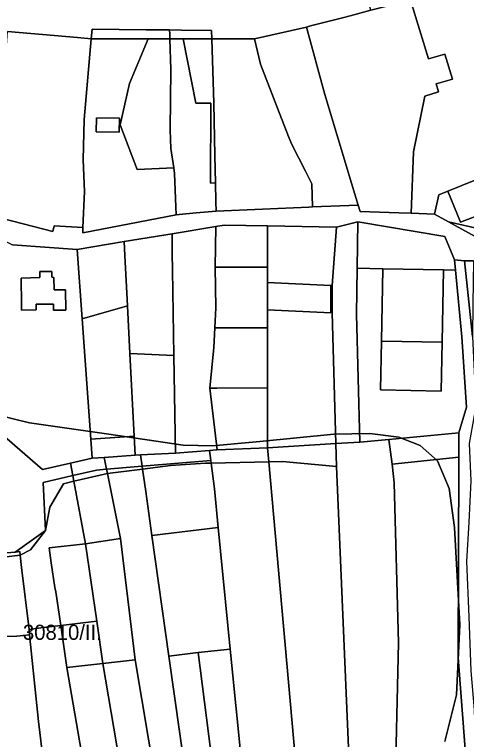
# Model space of a CAD drawing. Extents: x -535894 to -532834, y -1165802 to -1163645.
# Drawn here: x -534487.4 to -534338.4, y -1165184 to -1164945 of the extents above; entities that cross this region are included whole.
import ezdxf

# ---------------------------------------------------------------- set-up
doc = ezdxf.new("R2010")
doc.units = 0
for name, color, linetype in [('95560013', 7, 'Continuous'), ('95590013', 7, 'Continuous'), ('95600013', 7, 'Continuous'), ('95640013', 7, 'Continuous'), ('95660013', 7, 'Continuous')]:
    doc.layers.add(name, color=color, linetype=linetype)

msp = doc.modelspace()

# ---------------------------------------------------------------- linework, layer by layer
at = {"layer": '95560013'}
for points in [[(-534363.95, -1165085.07), (-534340.91, -1165082.87), (-534340.93, -1165090.96), (-534362.94, -1165093.25)], [(-534373.53, -1165086), (-534363.95, -1165085.07), (-534362.94, -1165093.25), (-534362.19, -1165099.37), (-534360.8, -1165152.21), (-534363.2, -1165257.26), (-534368.13, -1165254.92), (-534376.79, -1165251.88), (-534375.61, -1165225.35), (-534381.19, -1165093.99), (-534381.51, -1165086.49)], [(-534403.97, -1165087.87), (-534403.56, -1165092.47), (-534422.55, -1165092.92), (-534422.66, -1165092.09), (-534423.1, -1165088.71), (-534420.94, -1165088.56), (-534420.53, -1165088.55)], [(-534403.97, -1165087.87), (-534381.51, -1165086.49), (-534381.19, -1165093.99), (-534399.08, -1165092.35), (-534403.56, -1165092.47)], [(-534422.55, -1165092.92), (-534403.56, -1165092.47), (-534391.54, -1165226.66), (-534389.65, -1165251.4), (-534397.29, -1165252.4), (-534405.45, -1165253.73), (-534408.79, -1165228.57), (-534416.26, -1165154.3), (-534420.23, -1165114.18), (-534421.45, -1165101.43)], [(-534403.56, -1165092.47), (-534399.08, -1165092.35), (-534381.19, -1165093.99), (-534375.61, -1165225.35), (-534391.54, -1165226.66)], [(-534362.94, -1165093.25), (-534340.93, -1165090.96), (-534341.17, -1165157.05), (-534338.8, -1165187.24), (-534348.24, -1165186.88), (-534348.28, -1165269.23), (-534358.8, -1165260.74), (-534363.2, -1165257.26), (-534360.8, -1165152.21), (-534362.19, -1165099.37)], [(-534445.18, -1165094.85), (-534456.75, -1165096.28), (-534457.02, -1165094.93), (-534445.3, -1165093.96)], [(-534456.75, -1165096.28), (-534445.18, -1165094.85), (-534444.13, -1165102.22), (-534442.07, -1165116.76), (-534436.45, -1165156.54), (-534425.58, -1165233.37), (-534425.2, -1165235.77), (-534435.5, -1165237.88), (-534440.98, -1165197.04), (-534447.57, -1165157.79), (-534452.39, -1165117.81)], [(-534458.2, -1165158.95), (-534447.57, -1165157.79), (-534440.98, -1165197.04), (-534435.5, -1165237.88), (-534444.47, -1165239.8)]]:
    msp.add_lwpolyline(points, close=True, dxfattribs=at)
at = {"layer": '95590013'}
for points in [[(-534371.08, -1164939.34), (-534357.43, -1164937.18), (-534334.97, -1164941.39), (-534333.48, -1164948.48), (-534333.57, -1164963.39), (-534333.62, -1164973.53), (-534334.15, -1164983.38), (-534333.78, -1164990.52), (-534333.36, -1164998.76), (-534335.33, -1164999.55), (-534344.59, -1165003.27), (-534347.52, -1165004.44), (-534348.99, -1165010.79), (-534356.63, -1165010.51), (-534355.84, -1164990.24), (-534352.12, -1164971.86), (-534347.59, -1164970.48), (-534348.38, -1164967.88), (-534343.02, -1164966.25), (-534345.52, -1164958.02), (-534350.88, -1164959.65), (-534356.81, -1164940.14), (-534369.96, -1164943.59)], [(-534431.79, -1164953.01), (-534422.33, -1164953), (-534421.68, -1164974.24), (-534421.31, -1164991.48), (-534421.11, -1165000.5), (-534422.82, -1165000.59), (-534422.68, -1164974.25), (-534427.58, -1164974.26)], [(-534344.59, -1165003.27), (-534340.41, -1165013.49), (-534326.34, -1165008.07), (-534323.17, -1165006.94), (-534316.46, -1165011.48), (-534307.96, -1165011.06), (-534307.68, -1165013.89), (-534311.71, -1165018.18), (-534316.13, -1165017.8), (-534323.68, -1165017.15), (-534329.82, -1165016.63), (-534344.37, -1165013.33), (-534348.99, -1165010.79), (-534347.52, -1165004.44)], [(-534381.21, -1165015.12), (-534374.22, -1165013.39), (-534374.46, -1165028.64), (-534374.69, -1165043.74), (-534373.53, -1165086), (-534381.51, -1165086.49), (-534382.68, -1165043.37), (-534382.64, -1165034.37)], [(-534344.37, -1165013.33), (-534329.82, -1165016.63), (-534323.68, -1165017.15), (-534316.13, -1165017.8), (-534311.71, -1165018.18), (-534313.73, -1165020.34), (-534327.77, -1165022.47)], [(-534488.01, -1165020.91), (-534466.76, -1165022.45), (-534465.11, -1165045.38), (-534462.24, -1165085.02), (-534461.79, -1165091.28), (-534468.89, -1165092.92), (-534478.11, -1165095.05), (-534491.48, -1165083.48), (-534497.01, -1165041.71), (-534499.24, -1165024.85), (-534500.56, -1165014.81)], [(-534420.99, -1165014.89), (-534421.26, -1165028.31), (-534421.04, -1165041.75), (-534421.36, -1165048.3), (-534421.67, -1165054.78), (-534423.03, -1165068.16), (-534420.53, -1165088.55), (-534420.94, -1165088.56), (-534423.1, -1165088.71), (-534434.26, -1165089.65), (-534434.81, -1165057.43), (-534435.28, -1165029.23), (-534435.39, -1165023.63), (-534435.41, -1165017.27)], [(-534381.21, -1165015.12), (-534382.64, -1165034.37), (-534383.14, -1165034.35), (-534403.98, -1165033.35), (-534403.99, -1165028.33), (-534403.97, -1165014.71)], [(-534339, -1165026.19), (-534336.09, -1165026.21), (-534336.35, -1165040.51), (-534336.45, -1165051.12)], [(-534479.02, -1165029.69), (-534478.99, -1165031.69), (-534485.18, -1165031.88), (-534485.01, -1165040.52), (-534485.01, -1165042.48), (-534480.24, -1165042.39), (-534480.25, -1165040.49), (-534474.56, -1165040.45), (-534474.52, -1165042.52), (-534470.45, -1165042.5), (-534470.53, -1165035.74), (-534474.28, -1165035.76), (-534474.35, -1165031.67), (-534475.04, -1165031.63), (-534475.11, -1165029.69)], [(-534365.92, -1165028.8), (-534366.38, -1165052.71), (-534366.7, -1165068.79), (-534346.71, -1165069.18), (-534346.39, -1165053.08), (-534345.92, -1165029.2), (-534342.03, -1165029.27), (-534339.89, -1165051.28), (-534338.44, -1165074.49), (-534340.91, -1165082.87), (-534363.95, -1165085.07), (-534373.53, -1165086), (-534374.69, -1165043.74), (-534374.46, -1165028.64)], [(-534383.14, -1165034.35), (-534382.64, -1165034.37), (-534382.68, -1165043.37), (-534381.51, -1165086.49), (-534403.97, -1165087.87), (-534403.97, -1165068.1), (-534403.98, -1165048.34), (-534403.98, -1165042.36), (-534383.14, -1165043.35)], [(-534450.11, -1165041.01), (-534449.3, -1165056.79), (-534447.89, -1165084.07), (-534462.24, -1165085.02), (-534465.11, -1165045.38)], [(-534403.98, -1165048.34), (-534403.97, -1165068.1), (-534420.73, -1165068.15), (-534423.03, -1165068.16), (-534421.67, -1165054.78), (-534421.36, -1165048.3)], [(-534366.38, -1165052.71), (-534346.39, -1165053.08), (-534346.71, -1165069.18), (-534366.7, -1165068.79)], [(-534434.81, -1165057.43), (-534434.26, -1165089.65), (-534445.83, -1165090.22), (-534447.57, -1165090.34), (-534447.89, -1165084.07), (-534449.3, -1165056.79)], [(-534420.73, -1165068.15), (-534403.97, -1165068.1), (-534403.97, -1165087.87), (-534420.53, -1165088.55), (-534423.03, -1165068.16)], [(-534422.55, -1165092.92), (-534424.46, -1165092.97), (-534435.96, -1165093.7), (-534445.18, -1165094.85), (-534445.3, -1165093.96), (-534422.66, -1165092.09)], [(-534460.35, -1165095.21), (-534457.02, -1165094.93), (-534456.75, -1165096.28), (-534467.78, -1165098.88), (-534468.13, -1165097.01)], [(-534424.46, -1165092.97), (-534422.55, -1165092.92), (-534421.45, -1165101.43), (-534420.23, -1165114.18), (-534442.07, -1165116.76), (-534444.13, -1165102.22), (-534445.18, -1165094.85), (-534435.96, -1165093.7)], [(-534467.78, -1165098.88), (-534456.75, -1165096.28), (-534452.39, -1165117.81), (-534463.97, -1165119.47)], [(-534472.14, -1165146.47), (-534460.23, -1165145.05), (-534458.2, -1165158.95), (-534470.12, -1165160.31)], [(-534478.68, -1165147.25), (-534472.14, -1165146.47), (-534470.12, -1165160.31), (-534455.8, -1165243.06), (-534461.02, -1165244.38), (-534470.72, -1165237.94), (-534474.69, -1165217.27), (-534479.49, -1165178.1), (-534482.37, -1165149.5), (-534482.54, -1165147.81)], [(-534426.83, -1165155.34), (-534416.26, -1165154.3), (-534408.79, -1165228.57), (-534417.1, -1165232.13)], [(-534436.45, -1165156.54), (-534426.83, -1165155.34), (-534417.1, -1165232.13), (-534408.79, -1165228.57), (-534405.45, -1165253.73), (-534415.33, -1165254.24), (-534421.35, -1165253.74), (-534423.92, -1165242.4), (-534425.2, -1165235.77), (-534425.58, -1165233.37)], [(-534470.12, -1165160.31), (-534458.2, -1165158.95), (-534444.47, -1165239.8), (-534455.8, -1165243.06)]]:
    msp.add_lwpolyline(points, close=True, dxfattribs=at)
at = {"layer": '95600013'}
msp.add_lwpolyline([(-534526.42, -1165144.06), (-534506.66, -1165142.89), (-534505.88, -1165150.21), (-534486.55, -1165149.95), (-534482.37, -1165149.5), (-534479.49, -1165178.1), (-534474.69, -1165217.27), (-534470.72, -1165237.94), (-534490.64, -1165243.85), (-534498.4, -1165244.45), (-534504.24, -1165246.32), (-534515.07, -1165249.99), (-534525.69, -1165253.61), (-534525.52, -1165245.33), (-534526.56, -1165167.24), (-534526.49, -1165154.6)], close=True, dxfattribs=at)
at = {"layer": '95640013'}
for points in [[(-534356.81, -1164940.14), (-534350.88, -1164959.65), (-534345.52, -1164958.02), (-534343.02, -1164966.25), (-534348.38, -1164967.88), (-534347.59, -1164970.48), (-534352.12, -1164971.86), (-534355.84, -1164990.24), (-534356.63, -1165010.51), (-534360.64, -1165010.37), (-534373.42, -1165009.91), (-534374.04, -1165007.87), (-534376.24, -1165000.61), (-534385.1, -1164971.33), (-534391.17, -1164949.12), (-534389.78, -1164948.76), (-534379.25, -1164946.03), (-534376.73, -1164945.38), (-534369.96, -1164943.59)], [(-534391.17, -1164949.12), (-534385.1, -1164971.33), (-534376.24, -1165000.61), (-534374.04, -1165007.87), (-534389.11, -1165008.45), (-534389.4, -1165000.85), (-534391.5, -1164996.69), (-534395.95, -1164987.86), (-534396.87, -1164985.71), (-534400.13, -1164977.32), (-534406.33, -1164961.38), (-534408.23, -1164953)], [(-534466.57, -1164952.61), (-534462.09, -1164953), (-534464.37, -1164979.65), (-534464.75, -1164992.87), (-534464.33, -1165003.32), (-534464.79, -1165015.17), (-534474.29, -1165014.68), (-534474.77, -1165016.57), (-534494.86, -1165011.42), (-534497.44, -1165010.75), (-534499.22, -1165009.6), (-534494.31, -1165002.21), (-534492.53, -1164986.26), (-534492.33, -1164984.55), (-534491.63, -1164978.28), (-534489.63, -1164950.63)], [(-534461.81, -1164949.81), (-534443.96, -1164950), (-534442.32, -1164950.03), (-534436.91, -1164950.08), (-534436.26, -1164950.09), (-534436.21, -1164951.47), (-534436.16, -1164953), (-534443.26, -1164953), (-534445.31, -1164953), (-534462.09, -1164953)], [(-534436.26, -1164950.09), (-534432.36, -1164950.13), (-534422.4, -1164950.24), (-534422.33, -1164953), (-534431.79, -1164953.01), (-534436.16, -1164953), (-534436.21, -1164951.47)], [(-534462.09, -1164953), (-534445.31, -1164953), (-534443.26, -1164953), (-534449.41, -1164967.75), (-534452.51, -1164981.34), (-534446.93, -1164996.06), (-534434.88, -1164995.57), (-534434.58, -1164997.44), (-534434.2, -1165008.42), (-534434.11, -1165010.99), (-534464.85, -1165016.92), (-534464.79, -1165015.17), (-534464.33, -1165003.32), (-534464.75, -1164992.87), (-534464.37, -1164979.65)], [(-534443.26, -1164953), (-534436.16, -1164953), (-534435.79, -1164963.16), (-534436.1, -1164982.98), (-534435.88, -1164989.17), (-534434.88, -1164995.57), (-534446.93, -1164996.06), (-534452.51, -1164981.34), (-534449.41, -1164967.75)], [(-534436.16, -1164953), (-534431.79, -1164953.01), (-534427.58, -1164974.26), (-534422.68, -1164974.25), (-534422.82, -1165000.59), (-534421.11, -1165000.5), (-534420.98, -1165006.79), (-534420.92, -1165009.8), (-534427.49, -1165010.4), (-534433.05, -1165010.9), (-534434.11, -1165010.99), (-534434.2, -1165008.42), (-534434.58, -1164997.44), (-534434.88, -1164995.57), (-534435.88, -1164989.17), (-534436.1, -1164982.98), (-534435.79, -1164963.16)], [(-534422.33, -1164953), (-534408.23, -1164953), (-534406.33, -1164961.38), (-534400.13, -1164977.32), (-534396.87, -1164985.71), (-534395.95, -1164987.86), (-534391.5, -1164996.69), (-534389.4, -1165000.85), (-534389.11, -1165008.45), (-534390.4, -1165008.5), (-534420.92, -1165009.8), (-534420.98, -1165006.79), (-534421.11, -1165000.5), (-534421.31, -1164991.48), (-534421.68, -1164974.24)], [(-534460.38, -1164979.04), (-534452.78, -1164979.17), (-534452.83, -1164983.78), (-534460.47, -1164983.64)], [(-534460.38, -1164979.04), (-534460.47, -1164983.64), (-534452.83, -1164983.78), (-534452.78, -1164979.17)], [(-534326.13, -1164999.26), (-534323.17, -1165006.94), (-534326.34, -1165008.07), (-534340.41, -1165013.49), (-534344.59, -1165003.27), (-534335.33, -1164999.55), (-534334.18, -1165002.41), (-534329.35, -1165000.46), (-534328.08, -1164999.98)], [(-534374.22, -1165013.39), (-534345.52, -1165018.15), (-534342.35, -1165025.88), (-534342.03, -1165029.27), (-534345.92, -1165029.2), (-534365.92, -1165028.8), (-534374.46, -1165028.64)], [(-534403.97, -1165014.71), (-534403.99, -1165028.33), (-534407.71, -1165028.33), (-534419.68, -1165028.32), (-534421.26, -1165028.31), (-534420.99, -1165014.89), (-534418.3, -1165014.45)], [(-534435.41, -1165017.27), (-534435.39, -1165023.63), (-534435.28, -1165029.23), (-534434.81, -1165057.43), (-534449.3, -1165056.79), (-534450.11, -1165041.01), (-534450.96, -1165024.44), (-534451.2, -1165019.87)], [(-534451.2, -1165019.87), (-534450.96, -1165024.44), (-534450.11, -1165041.01), (-534465.11, -1165045.38), (-534466.76, -1165022.45)], [(-534342.35, -1165025.88), (-534339, -1165026.19), (-534336.45, -1165051.12), (-534335.3, -1165074.14), (-534337.54, -1165086.43), (-534336.94, -1165098.71), (-534337.66, -1165112.41), (-534338.34, -1165125.36), (-534337.61, -1165143.65), (-534336.91, -1165161.4), (-534335.9, -1165174.28), (-534335.39, -1165187.36), (-534338.8, -1165187.24), (-534341.17, -1165157.05), (-534340.93, -1165090.96), (-534340.91, -1165082.87), (-534338.44, -1165074.49), (-534339.89, -1165051.28), (-534342.03, -1165029.27)], [(-534479.02, -1165029.69), (-534475.11, -1165029.69), (-534475.04, -1165031.63), (-534474.35, -1165031.67), (-534474.28, -1165035.76), (-534470.53, -1165035.74), (-534470.45, -1165042.5), (-534474.52, -1165042.52), (-534474.56, -1165040.45), (-534480.25, -1165040.49), (-534480.24, -1165042.39), (-534485.01, -1165042.48), (-534485.01, -1165040.52), (-534485.18, -1165031.88), (-534478.99, -1165031.69)], [(-534419.68, -1165028.32), (-534407.71, -1165028.33), (-534403.99, -1165028.33), (-534403.98, -1165033.35), (-534403.98, -1165042.36), (-534403.98, -1165048.34), (-534421.36, -1165048.3), (-534421.04, -1165041.75), (-534421.26, -1165028.31)], [(-534345.92, -1165029.2), (-534346.39, -1165053.08), (-534366.38, -1165052.71), (-534365.92, -1165028.8)], [(-534403.98, -1165033.35), (-534383.14, -1165034.35), (-534383.14, -1165043.35), (-534403.98, -1165042.36)], [(-534447.89, -1165084.07), (-534447.57, -1165090.34), (-534457.81, -1165091.02), (-534461.79, -1165091.28), (-534462.24, -1165085.02)], [(-534447.57, -1165090.34), (-534445.83, -1165090.22), (-534445.3, -1165093.96), (-534457.02, -1165094.93), (-534457.81, -1165091.02)], [(-534434.26, -1165089.65), (-534423.1, -1165088.71), (-534422.66, -1165092.09), (-534445.3, -1165093.96), (-534445.83, -1165090.22)], [(-534461.79, -1165091.28), (-534457.81, -1165091.02), (-534457.02, -1165094.93), (-534460.35, -1165095.21), (-534468.13, -1165097.01), (-534468.89, -1165092.92)], [(-534467.78, -1165098.88), (-534471.25, -1165099.69), (-534475.74, -1165107.41), (-534477.12, -1165115.1), (-534477.91, -1165099.28), (-534468.13, -1165097.01)], [(-534471.25, -1165099.69), (-534467.78, -1165098.88), (-534463.97, -1165119.47), (-534475.96, -1165120.89), (-534475.24, -1165125.77), (-534474.04, -1165133.88), (-534473.77, -1165135.32), (-534472.14, -1165146.47), (-534478.68, -1165147.25), (-534482.54, -1165147.81), (-534485.11, -1165127.29), (-534485.47, -1165123.31), (-534482.11, -1165121.5), (-534477.12, -1165115.1), (-534475.74, -1165107.41)], [(-534442.07, -1165116.76), (-534420.23, -1165114.18), (-534416.26, -1165154.3), (-534426.83, -1165155.34), (-534436.45, -1165156.54)], [(-534482.11, -1165121.5), (-534485.47, -1165123.31), (-534485.59, -1165122.03), (-534487.16, -1165122.22), (-534477.12, -1165115.1)], [(-534463.97, -1165119.47), (-534452.39, -1165117.81), (-534447.57, -1165157.79), (-534458.2, -1165158.95), (-534460.23, -1165145.05)], [(-534463.97, -1165119.47), (-534460.23, -1165145.05), (-534472.14, -1165146.47), (-534473.77, -1165135.32), (-534474.04, -1165133.88), (-534475.24, -1165125.77), (-534475.96, -1165120.89)], [(-534485.59, -1165122.03), (-534485.47, -1165123.31), (-534508.47, -1165126.04), (-534508.71, -1165123.9), (-534487.16, -1165122.22)], [(-534508.47, -1165126.04), (-534485.47, -1165123.31), (-534485.11, -1165127.29), (-534482.54, -1165147.81), (-534482.37, -1165149.5), (-534486.55, -1165149.95), (-534505.88, -1165150.21), (-534506.66, -1165142.89), (-534507.16, -1165138.28), (-534508.07, -1165129.82)]]:
    msp.add_lwpolyline(points, close=True, dxfattribs=at)
for points in [[(-534369.96, -1164943.59), (-534376.73, -1164945.38), (-534379.25, -1164946.03), (-534389.78, -1164948.76), (-534391.17, -1164949.12), (-534408.23, -1164953), (-534422.33, -1164953), (-534422.4, -1164950.24), (-534432.36, -1164950.13), (-534436.26, -1164950.09), (-534436.91, -1164950.08), (-534442.32, -1164950.03), (-534443.96, -1164950), (-534461.81, -1164949.81), (-534462.09, -1164953), (-534466.57, -1164952.61), (-534489.63, -1164950.63)], [(-534494.86, -1165011.42), (-534474.77, -1165016.57), (-534474.29, -1165014.68), (-534464.79, -1165015.17), (-534464.85, -1165016.92), (-534434.11, -1165010.99), (-534433.05, -1165010.9), (-534427.49, -1165010.4), (-534420.92, -1165009.8), (-534390.4, -1165008.5), (-534389.11, -1165008.45), (-534374.04, -1165007.87), (-534373.42, -1165009.91), (-534360.64, -1165010.37), (-534356.63, -1165010.51), (-534348.99, -1165010.79), (-534344.37, -1165013.33), (-534327.77, -1165022.47)], [(-534336.09, -1165026.21), (-534339, -1165026.19), (-534342.35, -1165025.88), (-534345.52, -1165018.15), (-534374.22, -1165013.39), (-534381.21, -1165015.12), (-534403.97, -1165014.71), (-534418.3, -1165014.45), (-534420.99, -1165014.89), (-534435.41, -1165017.27), (-534451.2, -1165019.87), (-534466.76, -1165022.45), (-534488.01, -1165020.91)], [(-534491.48, -1165083.48), (-534478.11, -1165095.05), (-534468.89, -1165092.92), (-534468.13, -1165097.01), (-534477.91, -1165099.28), (-534477.12, -1165115.1), (-534487.16, -1165122.22), (-534508.71, -1165123.9)]]:
    msp.add_lwpolyline(points, dxfattribs=at)
at = {"layer": '95660013'}
for points in [[(-534345.52, -1165184.73), (-534341.69, -1165169.28), (-534340.58, -1165146.18), (-534342.33, -1165114.17), (-534344.08, -1165101.26), (-534347.997, -1165092.167), (-534353.64, -1165087.09), (-534360.73, -1165084.38), (-534370.2, -1165083.11), (-534382.16, -1165083.358), (-534406.52, -1165085.73), (-534422.13, -1165087.25), (-534431.76, -1165086.94), (-534457.09, -1165083.27), (-534482.42, -1165079.6), (-534517.62, -1165071)], [(-534517.62, -1165071), (-534482.42, -1165079.6), (-534457.09, -1165083.27), (-534431.76, -1165086.94), (-534422.13, -1165087.25), (-534406.52, -1165085.73), (-534382.16, -1165083.358), (-534370.2, -1165083.11), (-534360.73, -1165084.38), (-534353.64, -1165087.09), (-534347.997, -1165092.167), (-534344.08, -1165101.26), (-534342.33, -1165114.17), (-534340.58, -1165146.18), (-534341.69, -1165169.28), (-534345.52, -1165184.73)]]:
    msp.add_lwpolyline(points, dxfattribs=at)

# ---------------------------------------------------------------- texts
msp.add_text('30810/II.', height=5, rotation=0, dxfattribs=at).set_placement((-534484.594, -1165151.192))

doc.saveas('drawing.dxf')
